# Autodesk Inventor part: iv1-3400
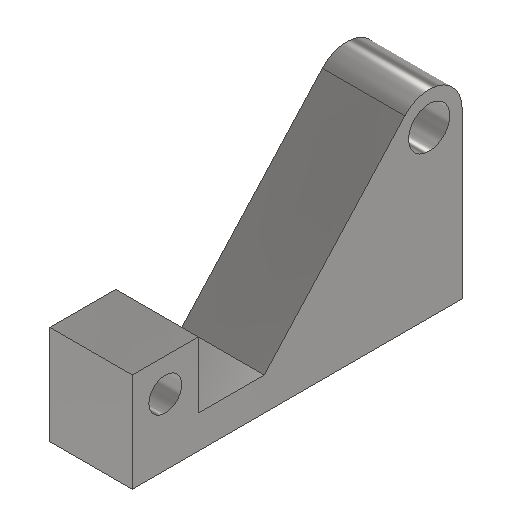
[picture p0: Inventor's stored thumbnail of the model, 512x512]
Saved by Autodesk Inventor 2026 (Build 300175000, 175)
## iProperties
Shininess: 64.0
Angle Display Precision: 2
Document Length Units: 11269
Document Angle Units: 11279
Document Time Units: 11290
Document Mass Units: 11283
Document Length Units Precision: 3
Document Angle Units Precision: 2
Compacted: True
Created: 2002-05
Part Number: iv1-3400
Document SubType Name: Modeling
Designer: Lars Bertram Pedersen
Material: Steel, Mild
Density: 7.85 g/cm^3
Appearance: Semi-Polished
Density: 0.0
Volumn: 0.0
Area: 0.0
PropertySet Name: Model Information
Control State: 0
Master: False
Checked Out: False
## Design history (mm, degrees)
sketch "Sketch1"
  geometry: L1 (0, 100)-(0, 0); L2 (0, 0)-(200, 0); L3 (200, 0)-(200, 51.697); L4 (160, 20)-(120, 20); L5 (120, 20)-(34.78, 113.475); L6 (200, 51.697)-(200, 60); L7 (200, 60)-(160, 60); L8 (160, 60)-(160, 20); C1 r 12.5 at (20, 100); C2 r 10 at (180, 40); A1 r 20 centre (20, 100) between (34.78, 113.475) and (0, 100); 1 further point
  constraints: 16 end point, 3 centre point, 3 parallel, 3 perpendicular, 2 coincident, 2 point on circle, 2 tangent, 1 vertical
  dimensions: "d9" = 200 distance of L1.end L2.end; "d15" = 25 diameter of C1; "d16" = 40 distance of L6.end L7.end; "d18" = 20 diameter of C2; "d19" = 20 distance from line of L7 C2.centre; "d20" = 20 distance from line of L8 C2.centre; "d21" = 80 horizontal distance of L6.end L4.end; "d22" = 100 distance from line of A1.centre L2; "d23" = 20 radius of A1 (derived); "d24" = 100 horizontal distance of A1.centre L4.end; "d26" = 20 distance between parallel lines of L2 L4; "d29" = 40 distance from line of L4.start L7
extrude "Extrusion1" new body sketch "Sketch1" distance "d27" = 50; taper "d28" = 0 deg
body "Solid1"
